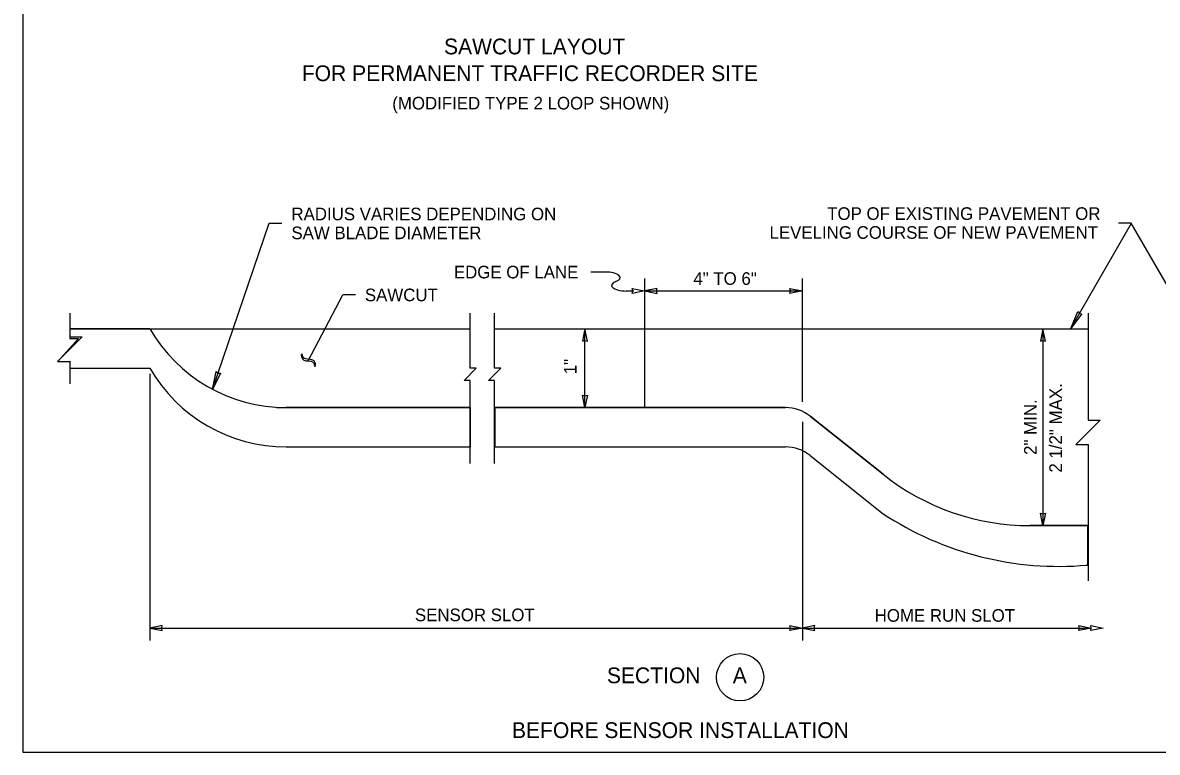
# Model space of a CAD drawing. Extents: x 99862 to 103151, y 100000 to 108076.
# Drawn here: x 99862 to 101303, y 100000 to 100926 of the extents above; entities that cross this region are included whole.
import ezdxf

# ---------------------------------------------------------------- set-up
doc = ezdxf.new("R2010")
doc.units = 0
for name, color, linetype in [('Level 1', 7, 'Continuous'), ('Level 15', 7, 'Continuous'), ('Level 2', 7, 'Continuous'), ('Level 20', 7, 'Continuous'), ('Level 34', 7, 'Continuous'), ('Level 60', 7, 'Continuous'), ('Level 9', 7, 'Continuous')]:
    doc.layers.add(name, color=color, linetype=linetype)

msp = doc.modelspace()

# ---------------------------------------------------------------- linework, layer by layer
at = {"layer": 'Level 1'}
msp.add_lwpolyline([(99862, 99999.5), (103151, 99999.5), (103151, 102075.5), (99862, 102075.5)], close=True, dxfattribs=at)
at = {"layer": 'Level 15'}
for p, q in [((100103.7, 100461.6), (100175.3, 100671.6)), ((100175.3, 100671.6), (100191.3, 100671.6)), ((101193.5, 100537.8), (101270.8, 100671.6)), ((101270.3, 100671.6), (101254.3, 100671.6)), ((101347.6, 100537.8), (101270.3, 100671.6)), ((100602.2, 100609.3), (100583.6, 100609.3)), ((100652.1, 100601.3), (100652.1, 100437.3)), ((100852.5, 100444.5), (100852.5, 100601.3)), ((100628.8, 100585.3), (100638.2, 100585.3)), ((100652.1, 100585.3), (100852.5, 100585.3)), ((100224.5, 100496.5), (100268.7, 100580.3)), ((100284.7, 100580.3), (100268.7, 100580.3)), ((100430.5, 100487.2), (100430.5, 100557.3)), ((100461.5, 100487.2), (100461.5, 100557.3)), ((100576.3, 100437.3), (100576.3, 100536.4)), ((101158.2, 100537.3), (101158.2, 100287.3)), ((100422.8, 100471.8), (100438.3, 100487.2)), ((100438.3, 100487.2), (100430.5, 100487.2)), ((100453.8, 100471.8), (100469.3, 100487.2)), ((100469.3, 100487.2), (100461.5, 100487.2)), ((100023.7, 100480.2), (100023.7, 100141.3)), ((100430.5, 100471.8), (100422.8, 100471.8)), ((100430.5, 100366.3), (100430.5, 100471.8)), ((100461.5, 100471.8), (100453.8, 100471.8)), ((100461.5, 100366.3), (100461.5, 100471.8)), ((100852.5, 100419.3), (100852.5, 100141.3)), ((100023.7, 100157.3), (100852.5, 100157.3)), ((100852.5, 100157.3), (101219.5, 100157.3))]:
    msp.add_line(p, q, dxfattribs=at)
for points in [[(100652.1, 100585.3), (100636.4, 100582.2), (100637.2, 100585.3), (100636.4, 100588.4)], [(100652.1, 100585.3), (100667.9, 100582.2), (100667.1, 100585.3), (100667.9, 100588.4)], [(100852.5, 100585.3), (100836.7, 100582.2), (100837.5, 100585.3), (100836.7, 100588.4)], [(101193.5, 100537.8), (101202.4, 100559.1), (101204.4, 100556.7), (101207.5, 100556.1)], [(100576.3, 100537.3), (100573.2, 100521.6), (100576.3, 100522.4), (100579.4, 100521.6)], [(101158.2, 100537.3), (101155.1, 100521.6), (101158.2, 100522.3), (101161.3, 100521.6)], [(100103.3, 100460.4), (100107.8, 100483), (100110.3, 100481), (100113.5, 100481)], [(100576.3, 100437.3), (100573.2, 100453), (100576.3, 100452.3), (100579.4, 100453)], [(101158.2, 100287.3), (101155.1, 100303), (101158.2, 100302.3), (101161.3, 100303)], [(100023.7, 100157.3), (100039.4, 100154.2), (100038.7, 100157.3), (100039.4, 100160.4)], [(100852.5, 100157.3), (100836.7, 100154.2), (100837.5, 100157.3), (100836.7, 100160.4)], [(100852.5, 100157.3), (100868.2, 100154.2), (100867.5, 100157.3), (100868.2, 100160.4)], [(101219.5, 100157.3), (101203.8, 100154.2), (101204.5, 100157.3), (101203.8, 100160.4)], [(101234.5, 100157.3), (101218.8, 100154.2), (101219.5, 100157.3), (101218.8, 100160.4)]]:
    msp.add_lwpolyline(points, close=True, dxfattribs=at)
for points in [[(99921.9, 100557.3), (99921.9, 100526.9), (99937.4, 100526.9), (99906.4, 100495.9), (99921.9, 100495.9), (99921.9, 100467.3)], [(101215.5, 100557.3), (101215.5, 100421.2), (101231, 100421.2), (101200.1, 100390.2), (101215.5, 100390.2), (101215.5, 100217.3)]]:
    msp.add_lwpolyline(points, dxfattribs=at)
for centre, start_param, end_param in [((100602.3, 100602.3), 5.497747, 7.861127), ((100628.8, 100592.3), 2.356226, 4.712389)]:
    msp.add_ellipse(centre, major_axis=(18.7, 0), ratio=0.375, start_param=start_param, end_param=end_param, dxfattribs=at)
at = {"layer": 'Level 2'}
for p, q in [((99921.9, 100537.3), (100023.6, 100537.3)), ((100023.6, 100537.3), (100430.9, 100537.3)), ((100461.9, 100537.3), (101215.5, 100537.3)), ((100184.4, 100437.3), (100430.9, 100437.3)), ((100461.9, 100437.3), (100831.1, 100437.3)), ((100862.3, 100426.4), (100955.2, 100352.5)), ((101141.9, 100287.3), (101215.3, 100287.3))]:
    msp.add_line(p, q, dxfattribs=at)
for centre, radius, start, end in [((100196.8, 100637.3), 200, 210, 270), ((100831.1, 100387.3), 50, 51.4993, 90), ((101141.9, 100587.3), 300, 231.4993, 270)]:
    msp.add_arc(centre, radius, start, end, dxfattribs=at)
at = {"layer": 'Level 20'}
for p, q in [((100217, 100505.5), (100215.9, 100503.6)), ((100215.9, 100503.6), (100216.3, 100501.5)), ((100216.3, 100501.5), (100217, 100499.9)), ((100218, 100501.9), (100217, 100505.5)), ((100217, 100499.9), (100217.9, 100498.6)), ((100217.9, 100498.6), (100219.2, 100497.6)), ((100218.9, 100500.5), (100218, 100501.9)), ((100219.9, 100499.6), (100218.9, 100500.5)), ((100219.2, 100497.6), (100221.5, 100496.7)), ((100221.3, 100499.1), (100219.9, 100499.6)), ((100223.8, 100498.9), (100221.3, 100499.1)), ((100228.2, 100498.5), (100223.8, 100498.9)), ((100230.7, 100497.6), (100228.2, 100498.5)), ((100232.1, 100496.5), (100230.7, 100497.6)), ((100221.5, 100496.7), (100225.6, 100496.4)), ((100225.6, 100496.4), (100228.2, 100496.2)), ((100228.2, 100496.2), (100230, 100495.5)), ((100230, 100495.5), (100231, 100494.7)), ((100231, 100494.7), (100231.8, 100493.6)), ((100231.8, 100493.6), (100232.4, 100492)), ((100233.1, 100495.1), (100232.1, 100496.5)), ((100232.4, 100492), (100233, 100489.6)), ((100233, 100489.6), (100234, 100491.5)), ((100233.8, 100493.4), (100233.1, 100495.1)), ((100234, 100491.5), (100233.8, 100493.4))]:
    msp.add_line(p, q, dxfattribs=at)
at = {"layer": 'Level 34'}
for points in [[(100023.6, 100537.3), (99921.9, 100537.3), (99921.9, 100525), (99933, 100525), (99906.5, 100495.9), (99906.5, 100495.9), (99921.9, 100496), (99922, 100491.8), (99922, 100488.5), (99922, 100487.3), (100023.6, 100487.3)], [(100196.8, 100387.3), (100430.9, 100387.3), (100430.9, 100437.3), (100196.8, 100437.3)], [(100831.1, 100437.3), (100652.1, 100437.3), (100576.3, 100437.3), (100461.9, 100437.3), (100461.9, 100387.3), (100831.1, 100387.3)], [(100955.2, 100352.5), (100862.3, 100426.4)], [(100862.3, 100376.4), (100955.2, 100302.5)], [(101215.2, 100247.1), (101215.2, 100287.3), (101174.2, 100287.3), (101141.9, 100287.3)], [(101214.2, 100237.3), (101215.2, 100238.2)], [(101215.2, 100246), (101215.2, 100247.1)], [(101215.2, 100238.2), (101215.2, 100246)]]:
    msp.add_lwpolyline(points, dxfattribs=at)
for centre, radius, start, end in [((100196.8, 100637.3), 200, 210, 270), ((100196.8, 100587.3), 200, 210, 270), ((100831.1, 100387.3), 50, 51.4993, 90), ((100831.1, 100337.3), 50, 51.4993, 90), ((101141.9, 100587.3), 300, 231.4993, 270), ((101178.4, 100641.8), 406.2, 236.655, 275.0573)]:
    msp.add_arc(centre, radius, start, end, dxfattribs=at)
at = {"layer": 'Level 60'}
msp.add_line((99862, 99999.5), (99862, 99999.5), dxfattribs=at)
at = {"layer": 'Level 9'}
msp.add_circle((100773.4, 100094.8), 30, dxfattribs=at)

# ---------------------------------------------------------------- texts
at = {"layer": 'Level 20'}
for s, height, p in [('  SAWCUT LAYOUT ', 20, (100382.4, 100885.8)), ('FOR PERMANENT TRAFFIC RECORDER SITE', 20, (100216.6, 100851.8)), ('EDGE OF LANE', 16, (100409.8, 100601.3)), ('SECTION', 20, (100604.2, 100087.2)), ('A', 20, (100764.1, 100087.2)), ('BEFORE SENSOR INSTALLATION', 20, (100483.6, 100017.6))]:
    msp.add_text(s, height=height, dxfattribs=at).set_placement(p)
for s, rotation, p in [('(MODIFIED TYPE 2 LOOP SHOWN)', 360, (100331.5, 100815.8)), ('RADIUS VARIES DEPENDING ON ', 360, (100203.4, 100675.1)), ('TOP OF EXISTING PAVEMENT OR', 360, (100884.1, 100675.6)), ('SAW BLADE DIAMETER', 360, (100203.4, 100651.1)), ('LEVELING COURSE OF NEW PAVEMENT', 360, (100810.8, 100651.6)), ('4" TO 6"', 360, (100714, 100593.1)), ('SAWCUT', 0, (100296.7, 100572.3)), ('1"', 90, (100565.6, 100479.5)), ('2 1/2" MAX.', 90, (101182.2, 100354.7)), ('2" MIN.', 90, (101150.2, 100377.1)), ('SENSOR SLOT', 360, (100360.3, 100166)), ('HOME RUN SLOT', 360, (100944.4, 100165.3))]:
    msp.add_text(s, height=16, rotation=rotation, dxfattribs=at).set_placement(p)

doc.saveas('drawing.dxf')
